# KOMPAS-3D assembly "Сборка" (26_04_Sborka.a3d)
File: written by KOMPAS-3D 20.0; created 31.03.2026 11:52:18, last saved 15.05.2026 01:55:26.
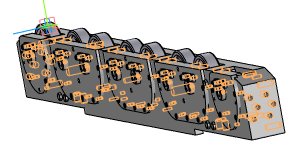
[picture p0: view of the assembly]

Document properties: Автор: taras; Полное имя файла: E:\test_kompas\all_v18\26_04_Sborka.a3d

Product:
- Part/product: Сборка
    Масса: 400.156
  - Component [standard]: Винт М12-6gx20 ГОСТ 11738-84  | qty 16  | pos. 31  | Масса: 0.03416; Раздел спецификации: Стандартные изделия; Рассекать на разрезах: no
  - Component [standard]: Болт М16-6gx170 ГОСТ 7795-70  | qty 6  | pos. 30  | Масса: 0.2633; Раздел спецификации: Стандартные изделия; Рассекать на разрезах: no
  - Component [standard]: Подшипник 318 ГОСТ 8338-75  | qty 7  | pos. 29  | Масса: 4.954; Раздел спецификации: Стандартные изделия; additional columns: 318
  - Component [detail]: Деталь  | pos. 28  | Масса: 0.134151; source file: ..\all_v22\Planka_rigelnaya (1).m3d
  - Component [detail]: Деталь  | pos. 27  | Масса: 0.134151; source file: ..\all_v22\Planka_rigelnaya (1).m3d
  - Component [detail]: Деталь  | pos. 26  | Масса: 0.134151; source file: ..\all_v22\Planka_rigelnaya (1).m3d
  - Component [detail]: Деталь  | pos. 25  | Масса: 0.134151; source file: ..\all_v22\Planka_rigelnaya (1).m3d
  - Component [detail]: Деталь  | pos. 24  | Масса: 0.134151; source file: ..\all_v22\Planka_rigelnaya (1).m3d
  - Component [detail]: Деталь  | pos. 23  | Масса: 0.134151; source file: ..\all_v22\Planka_rigelnaya (1).m3d
  - Component [detail]: Деталь  | pos. 22  | Масса: 0.134151; source file: ..\all_v22\Planka_rigelnaya (1).m3d
  - Component [detail]: Деталь  | pos. 21  | Масса: 0.134151; source file: ..\all_v22\Planka_rigelnaya (1).m3d
  - Component [detail]: Деталь  | pos. 20  | Масса: 2.04624; source file: ..\all_v22\Planka_rigelnaya (1).m3d
  - Component [detail]: Деталь  | pos. 19  | Масса: 2.04624; source file: ..\all_v22\Planka_rigelnaya (1).m3d
  - Component [standard]: Винт М10-6gx20 ГОСТ 11738-84  | qty 31  | pos. 17  | Масса: 0.02351; Раздел спецификации: Стандартные изделия; Рассекать на разрезах: no
  - Component [detail]: Деталь  | pos. 16  | Масса: 2.04624; source file: ..\all_v22\Planka_rigelnaya (1).m3d
  - Component [detail]: Деталь  | pos. 15  | Масса: 9.68884; source file: ..\all_v22\Planka_rigelnaya (1).m3d
  - Component [detail]: Деталь  | pos. 14  | Масса: 2.04624; source file: ..\all_v22\Planka_rigelnaya (1).m3d
  - Component [detail]: Деталь  | pos. 13  | Масса: 2.04624; source file: ..\all_v22\Planka_rigelnaya (1).m3d
  - Component [detail]: Деталь  | pos. 12  | Масса: 19.9484; source file: ..\all_v22\Planka_rigelnaya (1).m3d
  - Component [detail]: Деталь  | pos. 8  | Масса: 2.04624; source file: ..\all_v22\Planka_rigelnaya (1).m3d
  - Component [detail]: Деталь  | pos. 7  | Масса: 2.04624; source file: ..\all_v22\Planka_rigelnaya (1).m3d
  - Component [detail]: Деталь  | pos. 6  | Масса: 2.04624; source file: ..\all_v22\Planka_rigelnaya (1).m3d
  - Component [detail]: Деталь  | pos. 5  | Масса: 9.68884; source file: ..\all_v22\Planka_rigelnaya (1).m3d
  - Component [detail]: Деталь  | pos. 4  | Масса: 21.9342; source file: ..\all_v22\Planka_rigelnaya (1).m3d
  - Component [detail]: Деталь  | pos. 3  | Масса: 21.9342; source file: ..\all_v22\Planka_rigelnaya (1).m3d
  - Component [detail]: Деталь  | pos. 2  | Масса: 261.985; source file: ..\all_v22\Planka_rigelnaya (1).m3d
  - unknown [standard]: Винт М12-6gx20 ГОСТ 11738-84  | pos. 31
      Масса: 0.03416
      Раздел спецификации: Стандартные изделия
      Рассекать на разрезах: no
  - unknown [standard]: Болт М16-6gx170 ГОСТ 7795-70  | pos. 30
      Масса: 0.2633
      Раздел спецификации: Стандартные изделия
      Рассекать на разрезах: no
  - unknown [standard]: Подшипник 318 ГОСТ 8338-75  | pos. 29
      Масса: 4.954
      Раздел спецификации: Стандартные изделия
      additional columns: 318
  - unknown [detail]: Деталь  | pos. 28
      Масса: 0.134151
      Организация: TMK
      Автор: TMK
  - unknown [detail]: Деталь  | pos. 27
      Масса: 0.134151
      Организация: TMK
      Автор: TMK
  - unknown [detail]: Деталь  | pos. 26
      Масса: 0.134151
      Организация: TMK
      Автор: TMK
  - unknown [detail]: Деталь  | pos. 25
      Масса: 0.134151
      Организация: TMK
      Автор: TMK
  - unknown [detail]: Деталь  | pos. 24
      Масса: 0.134151
      Организация: TMK
      Автор: TMK
  - unknown [detail]: Деталь  | pos. 23
      Масса: 0.134151
      Организация: TMK
      Автор: TMK
  - unknown [detail]: Деталь  | pos. 22
      Масса: 0.134151
      Организация: TMK
      Автор: TMK
  - unknown [detail]: Деталь  | pos. 21
      Масса: 0.134151
      Организация: TMK
      Автор: TMK
  - unknown [detail]: Деталь  | pos. 20
      Масса: 2.04624
      Организация: TMK
      Автор: TMK
  - unknown [detail]: Деталь  | pos. 19
      Масса: 2.04624
      Организация: TMK
      Автор: TMK
  - unknown [detail]: Деталь  | pos. 16
      Масса: 2.04624
      Организация: TMK
      Автор: TMK
  - unknown [detail]: Деталь  | pos. 14
      Масса: 2.04624
      Организация: TMK
      Автор: TMK
  - unknown [detail]: Деталь  | pos. 13
      Масса: 2.04624
      Организация: TMK
      Автор: TMK
  - unknown [detail]: Деталь  | pos. 8
      Масса: 2.04624
      Организация: TMK
      Автор: TMK
  - unknown [detail]: Деталь  | pos. 7
      Масса: 2.04624
      Организация: TMK
      Автор: TMK
  - unknown [detail]: Деталь  | pos. 6
      Масса: 2.04624
      Организация: TMK
      Автор: TMK
  - unknown [standard]: Винт М10-6gx20 ГОСТ 11738-84  | pos. 17
      Масса: 0.02351
      Раздел спецификации: Стандартные изделия
      Рассекать на разрезах: no
  - unknown [detail]: Деталь  | pos. 15
      Масса: 9.68883
  - unknown [detail]: Деталь  | pos. 12
      Масса: 19.9484
      Автор: taras
  - unknown [detail]: Деталь  | pos. 5
      Масса: 9.68883
  - unknown [detail]: Деталь  | pos. 4
      Масса: 21.9342
      Организация: TMK
      Автор: TMK
  - unknown [detail]: Деталь  | pos. 3
      Масса: 21.9342
      Организация: TMK
      Автор: TMK
  - unknown [detail]: Деталь  | pos. 2
      Масса: 261.985

Referenced files in E:\test_kompas\all_v22\: Planka_rigelnaya (1).m3d
Referenced files in C:\Program Files\ASCON\KOMPAS-3D v20\Libs\PartLib\DATA\VAULT\methods\kompas\3d\: PLib_Screw_GOST_11738_1500.m3d, PLib_Bolt_1_900.m3d
Referenced files in C:\Program Files\ASCON\KOMPAS-3D v22\Libs\PolynomLib\DATA\vault\Methods\Kompas\3D\: PLib_Screw_GOST_11738_1500.m3d, PLib_Bolt_1_900.m3d
Referenced files in C:\Program Files\ASCON\KOMPAS-3D v20\Libs\PartLib\DATA\VAULT\methods\kompas\3d\Bearings\8338_75\: PLib_Bearing_GOST_8338_75_712.a3d
Referenced files in C:\Program Files\ASCON\KOMPAS-3D v22\Libs\PolynomLib\DATA\vault\Methods\Kompas\3D\Bearings\8338_75\: PLib_Bearing_GOST_8338_75_712.a3d
Referenced files in E:\test_kompas\all_v20\: 3.1.8 дет.45 Балка(оригинал) (1).m3d, 3.1.8  дет.46.2 Крышка балки (2).m3d, Крышка балки 1 окончательная (3).m3d, 3.1.8 дет.74 Ось кронштейна крепления опорного ролика(новый блок) (1).m3d, 05.04 крышка200.m3d, Planka_rigelnaya (1).m3d
Referenced files in C:\Program Files\ASCON\KOMPAS-3D v23 Study\Libs\PolynomLib\DATA\vault\Methods\Kompas\3D\: PLib_Screw_GOST_11738_1500.m3d, PLib_Bolt_1_900.m3d
Referenced files in C:\Program Files\ASCON\KOMPAS-3D v23 Study\Libs\PolynomLib\DATA\vault\Methods\Kompas\3D\Bearings\8338_75\: PLib_Bearing_GOST_8338_75_712.a3d
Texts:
  BOSimple***PART:419c87c2-70e2-98da-c2de-5eacb226740c***SHORTLOC:Root±30±20±10±80±10±GMC90[Нет;Без покрытия;Без указания материала;1,5;-;20;10]
  Крепежное изделие ГОСТ
  BOSimple***PART:61ab3e34-d848-86f0-c4aa-2b99c9f755c6***SHORTLOC:Root±Pac-16±Pac10±GMC20±GMC30±GMC10±GMC24[90;190;43]
  BOSimple***PART:9b7fe62b-1d30-3d6e-6be6-01a0e1891a36***SHORTLOC:Root±30±20±10±80±10±©{}30±©{BASE}130±190[Нет;Без покрытия;Без указания материала;170;16;22;2;-]
  BOSimple***PART:d3aa4c40-18a1-862e-ff95-3d42db175957***SHORTLOC:Root±30±20±10±80±10±GMC90[Нет;Без покрытия;Без указания материала;1,75;-;20;12]
  Деталь (1)
  Деталь (2)
  Деталь (3)
  Деталь (4)
  Деталь (5)
  Деталь (6)
  Винт М10-6gx20 ГОСТ 11738-84 (1)
  Винт М10-6gx20 ГОСТ 11738-84 (2)
  Винт М10-6gx20 ГОСТ 11738-84 (3)
  Винт М10-6gx20 ГОСТ 11738-84 (4)
  Винт М10-6gx20 ГОСТ 11738-84 (5)
  Винт М10-6gx20 ГОСТ 11738-84 (6)
  Винт М10-6gx20 ГОСТ 11738-84 (7)
  Винт М10-6gx20 ГОСТ 11738-84 (8)
  Винт М10-6gx20 ГОСТ 11738-84 (9)
  Винт М10-6gx20 ГОСТ 11738-84 (10)
  Винт М10-6gx20 ГОСТ 11738-84 (11)
  Винт М10-6gx20 ГОСТ 11738-84 (12)
  Винт М10-6gx20 ГОСТ 11738-84 (13)
  Винт М10-6gx20 ГОСТ 11738-84 (14)
  Винт М10-6gx20 ГОСТ 11738-84 (15)
  Винт М10-6gx20 ГОСТ 11738-84 (16)
  Винт М10-6gx20 ГОСТ 11738-84 (17)
  Винт М10-6gx20 ГОСТ 11738-84 (18)
  Винт М10-6gx20 ГОСТ 11738-84 (19)
  Винт М10-6gx20 ГОСТ 11738-84 (20)
  Винт М10-6gx20 ГОСТ 11738-84 (21)
  Винт М10-6gx20 ГОСТ 11738-84 (22)
  Винт М10-6gx20 ГОСТ 11738-84 (23)
  Винт М10-6gx20 ГОСТ 11738-84 (24)
  Винт М10-6gx20 ГОСТ 11738-84 (25)
  Винт М10-6gx20 ГОСТ 11738-84 (26)
  Винт М10-6gx20 ГОСТ 11738-84 (27)
  Винт М10-6gx20 ГОСТ 11738-84 (28)
  Винт М10-6gx20 ГОСТ 11738-84 (29)
  Винт М10-6gx20 ГОСТ 11738-84 (30)
  Винт М10-6gx20 ГОСТ 11738-84 (31)
  Деталь (7)
  Деталь (8)
  Подшипник 318 ГОСТ 8338-75 (1)
  Подшипник 318 ГОСТ 8338-75 (2)
  Подшипник 318 ГОСТ 8338-75 (3)
  Подшипник 318 ГОСТ 8338-75 (4)
  Подшипник 318 ГОСТ 8338-75 (5)
  Подшипник 318 ГОСТ 8338-75 (6)
  Подшипник 318 ГОСТ 8338-75 (7)
  Болт М16-6gx170 ГОСТ 7795-70 (1)
  hole1
  hole2
  Болт М16-6gx170 ГОСТ 7795-70 (2)
  Болт М16-6gx170 ГОСТ 7795-70 (3)
  Болт М16-6gx170 ГОСТ 7795-70 (4)
  Болт М16-6gx170 ГОСТ 7795-70 (5)
  Болт М16-6gx170 ГОСТ 7795-70 (6)
  Винт М12-6gx20 ГОСТ 11738-84 (1)
  Винт М12-6gx20 ГОСТ 11738-84 (2)
  Винт М12-6gx20 ГОСТ 11738-84 (3)
  Винт М12-6gx20 ГОСТ 11738-84 (4)
  Винт М12-6gx20 ГОСТ 11738-84 (5)
  Винт М12-6gx20 ГОСТ 11738-84 (6)
  Винт М12-6gx20 ГОСТ 11738-84 (7)
  Винт М12-6gx20 ГОСТ 11738-84 (8)
  Винт М12-6gx20 ГОСТ 11738-84 (9)
  Винт М12-6gx20 ГОСТ 11738-84 (10)
  Винт М12-6gx20 ГОСТ 11738-84 (11)
  Винт М12-6gx20 ГОСТ 11738-84 (12)
  Винт М12-6gx20 ГОСТ 11738-84 (13)
  Винт М12-6gx20 ГОСТ 11738-84 (14)
  Винт М12-6gx20 ГОСТ 11738-84 (15)
  Винт М12-6gx20 ГОСТ 11738-84 (16)
  Радус под головкой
